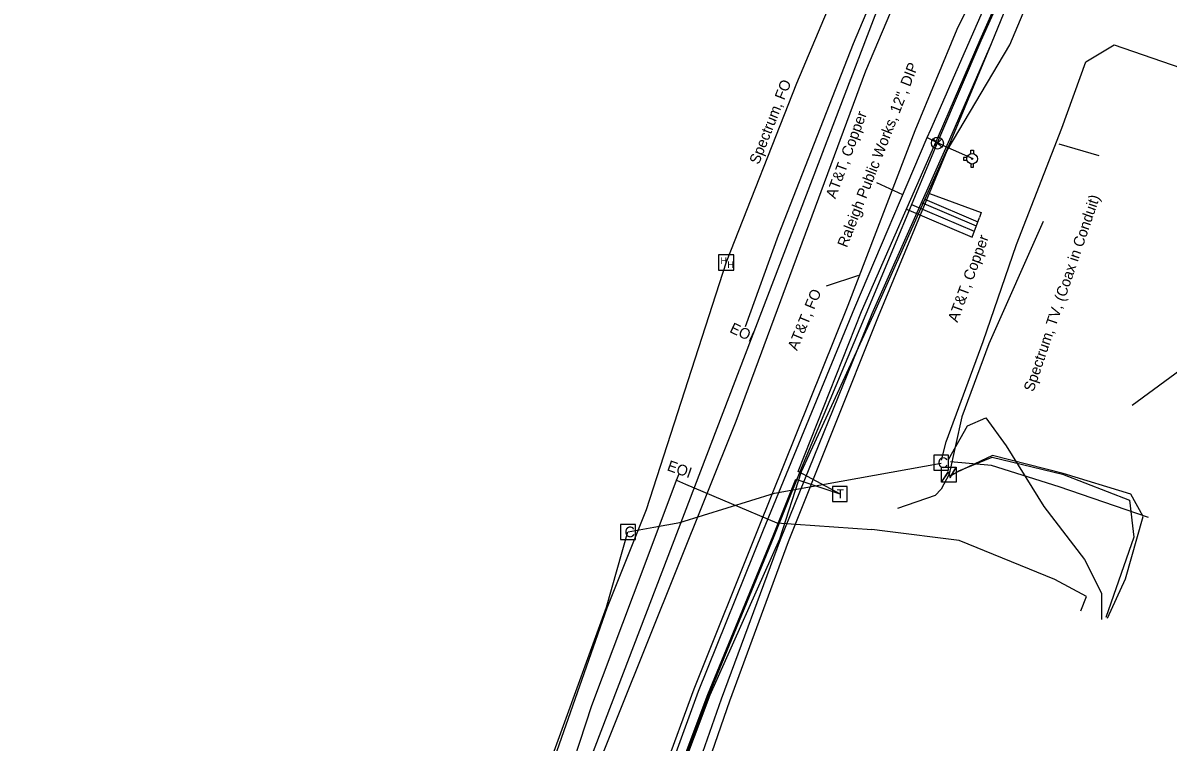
# Model space of a CAD drawing. Extents: x 2070721 to 2083039, y 729290 to 737883.
# Drawn here: x 2081151.9 to 2081580.5, y 733973 to 734242 of the extents above; entities that cross this region are included whole.
import ezdxf

# ---------------------------------------------------------------- set-up
doc = ezdxf.new("R2010")
doc.units = 0
for name, color, linetype in [('Cogo Default Point CELL', 7, 'Continuous'), ('COGO Default Point Elevation', 7, 'Continuous'), ('COGO Default Point Number', 7, 'Continuous'), ('Exist Utilities Gas UG Line SUE Cogo Point CELL', 7, 'Continuous'), ('Exist Utilities Gas UG Line SUE LOS B Cogo Comment', 7, 'Continuous'), ('Exist Utilities Gas UG Line SUE LOS B Cogo Point CELL', 7, 'Continuous'), ('Exist Utilities Gas Valve Cogo Elevation', 7, 'Continuous'), ('Exist Utilities Other Unknown UG SUE Cogo Point CELL', 7, 'Continuous'), ('Exist Utilities Power UG Cable SUE LOS B Cogo Elevation', 7, 'Continuous'), ('Exist Utilities Power UG Cable SUE LOS B Cogo Point CELL', 7, 'Continuous'), ('Exist Utilities Telephone UG Cable Cogo Point CELL', 7, 'Continuous'), ('Exist Utilities Telephone UG Cable SUE LOS C Cogo Comment', 7, 'Continuous'), ('Exist Utilities Telephone UG Cable SUE LOS C Cogo Number', 7, 'Continuous'), ('Exist Utilities Telephone UG FO SUE LOS B Cogo Comment', 7, 'Continuous'), ('Exist Utilities TV Hand Hole CELL', 7, 'Continuous'), ('Exist Utilities TV Pedestal CELL', 7, 'Continuous'), ('Exist Utilities TV Pedestal Cogo Elevation', 7, 'Continuous'), ('Exist Utilities TV Pedestal Cogo Number', 7, 'Continuous'), ('Exist Utilities TV UG Cable Cogo Point CELL', 7, 'Continuous'), ('Exist Utilities TV UG Cable SUE LOS C Cogo Comment', 7, 'Continuous'), ('Exist Utilities TV UG Cable SUE LOS C Cogo Elevation', 7, 'Continuous'), ('Exist Utilities TV UG Cable SUE LOS C Cogo Number', 7, 'Continuous'), ('Exist Utilities TV UG Cable SUE LOS C Cogo Point CELL', 7, 'Continuous'), ('Exist Utilities Water Manhole Cogo Elevation', 7, 'Continuous'), ('Exist Utilities Water Manhole Cogo Number', 7, 'Continuous'), ('Exist Utilities Water Meter Cogo Number', 7, 'Continuous')]:
    doc.layers.add(name, color=color, linetype=linetype)

msp = doc.modelspace()

# ---------------------------------------------------------------- linework, layer by layer
at = {"layer": 'Cogo Default Point CELL'}
for p, q in [((2081495.55, 734077.52), (2081495.55, 734077.52)), ((2081378.38, 734051.63), (2081378.38, 734051.63))]:
    msp.add_line(p, q, dxfattribs=at)
for points in [[(2081492.78, 734074.75), (2081498.33, 734074.75), (2081498.33, 734080.3), (2081492.78, 734080.3), (2081492.78, 734074.75)], [(2081375.61, 734048.85), (2081381.16, 734048.85), (2081381.16, 734054.4), (2081375.61, 734054.4), (2081375.61, 734048.85)]]:
    msp.add_lwpolyline(points, dxfattribs=at)
at = {"layer": 'COGO Default Point Elevation'}
msp.add_lwpolyline([(2081495.74, 734198.64), (2081492.59, 734195.49), (2081494.16, 734197.07), (2081495.74, 734195.49), (2081492.59, 734198.64)], dxfattribs=at)
msp.add_circle((2081494.16, 734197.07), 2.23, dxfattribs=at)
at = {"layer": 'COGO Default Point Number'}
msp.add_line((2081507.14, 734191.19), (2081507.14, 734191.19), dxfattribs=at)
for points in [[(2081505.23, 734191.7), (2081503.94, 734191.7), (2081503.94, 734190.67), (2081505.23, 734190.67)], [(2081506.62, 734193.1), (2081506.62, 734194.39), (2081507.65, 734194.39), (2081507.65, 734193.07)], [(2081506.62, 734189.27), (2081506.62, 734187.99), (2081507.65, 734187.99), (2081507.65, 734189.3)]]:
    msp.add_lwpolyline(points, dxfattribs=at)
for radius in [1.98, 0.243]:
    msp.add_circle((2081507.14, 734191.19), radius, dxfattribs=at)
at = {"layer": 'Exist Utilities Gas Valve Cogo Elevation'}
for p, q in [((2081488.23, 734174.81), (2081508.68, 734166.13)), ((2081489.45, 734176.03), (2081509.23, 734167.66)), ((2081484.48, 734174.03), (2081507.94, 734164.17))]:
    msp.add_line(p, q, dxfattribs=at)
for points in [[(2081491.14, 734178.26), (2081510.46, 734171.14), (2081509.82, 734169.24)], [(2081482.62, 734172.39), (2081507.12, 734161.92), (2081509.82, 734169.24)]]:
    msp.add_lwpolyline(points, dxfattribs=at)
at = {"layer": 'Exist Utilities Other Unknown UG SUE Cogo Point CELL'}
msp.add_line((2081539.58, 734196.78), (2081554.51, 734192.46), dxfattribs=at)
at = {"layer": 'Exist Utilities Telephone UG Cable Cogo Point CELL'}
msp.add_line((2081415.06, 734152.42), (2081415.06, 734152.42), dxfattribs=at)
msp.add_lwpolyline([(2081412.19, 734149.55), (2081417.94, 734149.55), (2081417.94, 734155.3), (2081412.19, 734155.3), (2081412.19, 734149.55)], dxfattribs=at)
at = {"layer": 'Exist Utilities Telephone UG Cable SUE LOS C Cogo Comment'}
for points in [[(2081306.2, 733834.68), (2081331.52, 733896.97), (2081357.74, 733949.48), (2081551.49, 734455.55)], [(2081422.3, 734128.51), (2081434.71, 734162.6), (2081462.76, 734234.36), (2081499.05, 734320.38), (2081503.56, 734331.04)]]:
    msp.add_lwpolyline(points, dxfattribs=at)
at = {"layer": 'Exist Utilities Telephone UG Cable SUE LOS C Cogo Number'}
msp.add_line((2081498.49, 734073.2), (2081498.49, 734073.2), dxfattribs=at)
msp.add_lwpolyline([(2081495.64, 734075.81), (2081501.2, 734075.81), (2081501.2, 734070.26), (2081495.64, 734070.26)], close=True, dxfattribs=at)
for points in [[(2081495.64, 734070.26), (2081498.29, 734074.2), (2081498.92, 734071.99), (2081501.2, 734075.81)], [(2081495.71, 734070.26), (2081498.29, 734073.99), (2081498.87, 734071.81), (2081501.2, 734075.66)]]:
    msp.add_lwpolyline(points, dxfattribs=at)
at = {"layer": 'Exist Utilities Telephone UG FO SUE LOS B Cogo Comment'}
msp.add_line((2081457.55, 734065.88), (2081457.55, 734065.88), dxfattribs=at)
msp.add_lwpolyline([(2081454.82, 734063.06), (2081460.42, 734063.06), (2081460.42, 734068.65), (2081454.82, 734068.65), (2081454.82, 734063.06)], dxfattribs=at)
at = {"layer": 'Exist Utilities TV Hand Hole CELL'}
msp.add_line((2081481.14, 734177.71), (2081471.52, 734182.16), dxfattribs=at)
at = {"layer": 'Exist Utilities TV Pedestal CELL'}
msp.add_lwpolyline([(2081305.07, 733834.62), (2081318.51, 733883.96), (2081344.94, 733950.24), (2081370.6, 734023.22), (2081385.26, 734060), (2081415.18, 734152.65), (2081441.55, 734219.41), (2081473.57, 734295.5), (2081490.54, 734320.82), (2081495.24, 734327.83)], dxfattribs=at)
at = {"layer": 'Exist Utilities TV Pedestal Cogo Elevation'}
for points in [[(2081490.29, 734199.14), (2081491.68, 734202.17), (2081522.1, 734271.61), (2081541.68, 734313.21), (2081545.19, 734320.14)], [(2081335.25, 733795.02), (2081336.53, 733799.05), (2081370.86, 733898.95), (2081404.78, 733992.12), (2081429.05, 734052.38), (2081463.19, 734135.61), (2081490.29, 734199.14)], [(2081490.29, 734199.14), (2081496.9, 734195.96), (2081507.42, 734191.29)]]:
    msp.add_lwpolyline(points, dxfattribs=at)
at = {"layer": 'Exist Utilities TV Pedestal Cogo Number'}
for points in [[(2081338.03, 733905.19), (2081338.21, 733905.54), (2081364.78, 733986.66), (2081384.36, 734038.69), (2081396.54, 734070.93), (2081397.51, 734073.37)], [(2081396.54, 734070.93), (2081399.83, 734069.53), (2081434.09, 734054.98), (2081469.65, 734052.56)], [(2081547.78, 734022.11), (2081549.89, 734027.5), (2081538.01, 734033.8), (2081502.22, 734048.37), (2081474.49, 734051.91), (2081469.65, 734052.56)]]:
    msp.add_lwpolyline(points, dxfattribs=at)
at = {"layer": 'Exist Utilities TV UG Cable Cogo Point CELL'}
for points in [[(2080953.21, 732796.69), (2081054.09, 733077.62), (2081111.09, 733245.57), (2081176.08, 733423.78), (2081231.97, 733580.28), (2081320.16, 733847.08), (2081418.84, 734093.09), (2081467.34, 734224.03), (2081494.06, 734287.2), (2081526.74, 734352.01), (2081556, 734404.62), (2081808.13, 734757.73), (2081845.73, 734804.26), (2081874.67, 734821.58), (2081898.66, 734810.94), (2081917.15, 734795.51)], [(2081296.4, 733658.15), (2081287.8, 733664.8), (2081303.6, 733706.37), (2081324.3, 733763.14), (2081337.34, 733798.98), (2081373.91, 733899.45), (2081408.19, 733990.78), (2081432.67, 734050.1), (2081441.11, 734071.31), (2081457.65, 734065.9), (2081441.97, 734074.17), (2081465.76, 734134.1), (2081494.56, 734199.64), (2081510.1, 734235.63), (2081525.23, 734269.67), (2081532.48, 734287.03), (2081544.5, 734311.63), (2081547.42, 734317.11)], [(2081296.31, 733658.4), (2081289.16, 733664.06), (2081304.03, 733706.05), (2081324.8, 733762.93), (2081337.87, 733799.07), (2081374.5, 733899.39), (2081408.89, 733991.2), (2081433.1, 734049.99), (2081442.72, 734074.23), (2081467.51, 734133.17), (2081494.99, 734199.31), (2081510.48, 734235.4), (2081525.69, 734269.34), (2081544.76, 734311.53), (2081547.99, 734317.07)], [(2081296.39, 733658.2), (2081307.45, 733685.25), (2081318.77, 733704.29), (2081345.73, 733792.08), (2081384.21, 733895.19), (2081416.52, 733988.47), (2081438.43, 734048.05), (2081472.15, 734132.3), (2081497.77, 734194.3), (2081521.27, 734233.79), (2081552.24, 734307.58), (2081554.35, 734311.73)], [(2081296.32, 733658.45), (2081292.23, 733667.87), (2081304.13, 733678.02), (2081310.51, 733703.91), (2081344.1, 733799.36), (2081380.98, 733896.99), (2081413.3, 733989.25), (2081435.43, 734048.8), (2081469.68, 734133.31), (2081498.8, 734198.46), (2081514.35, 734234.28), (2081535.34, 734285.71)], [(2081296.61, 733659.46), (2081294.36, 733663.37), (2081305.04, 733689.21), (2081304.27, 733706.32), (2081325.1, 733762.82), (2081338.41, 733798.86), (2081374.68, 733899.14), (2081409.12, 733990.75), (2081435.11, 734049.06), (2081443.22, 734074.28), (2081470.18, 734132.86), (2081499.3, 734198.06), (2081514.4, 734234.31)]]:
    msp.add_lwpolyline(points, dxfattribs=at)
at = {"layer": 'Exist Utilities TV UG Cable SUE LOS C Cogo Comment'}
for points in [[(2081566.99, 734098.99), (2081593.32, 734118.39), (2081609.81, 734133.03), (2081619.44, 734166.59), (2081611.13, 734190.33), (2081606.68, 734198.77)], [(2081533.76, 734167.78), (2081513.41, 734122.01), (2081503.32, 734094.68), (2081498.5, 734073.2)], [(2081557.74, 734019.38), (2081564.5, 734034.09), (2081571.11, 734057.42), (2081566.57, 734065.71), (2081541.21, 734073.53), (2081514.71, 734080.22), (2081499.18, 734072.89)], [(2081499.39, 734072.79), (2081502.13, 734074.42), (2081514.62, 734079.56), (2081541, 734073.24), (2081566.01, 734063.53), (2081567.68, 734049.7), (2081557.19, 734019.59)], [(2081498.49, 734073.2), (2081495.51, 734067.56), (2081493.34, 734065.2), (2081479.14, 734060.39)]]:
    msp.add_lwpolyline(points, dxfattribs=at)
at = {"layer": 'Exist Utilities TV UG Cable SUE LOS C Cogo Elevation'}
msp.add_lwpolyline([(2081311.88, 733857.73), (2081318.02, 733883.97), (2081343.7, 733950.47), (2081370.25, 734023.44), (2081378.31, 734051.68)], dxfattribs=at)
at = {"layer": 'Exist Utilities TV UG Cable SUE LOS C Cogo Number'}
for points in [[(2081495.68, 734078.41), (2081497.44, 734085.32), (2081511.29, 734122.81), (2081523.68, 734159.18), (2081540.68, 734202.67), (2081549.71, 734227.45), (2081560.24, 734233.78), (2081599.68, 734220.27), (2081626.49, 734212.19), (2081636.02, 734210.48)], [(2081498.25, 734078.67), (2081505.35, 734091.29), (2081512.22, 734094.34), (2081519.8, 734083.82), (2081533.95, 734061.11), (2081549.19, 734041.27), (2081555.57, 734028.72), (2081555.57, 734018.83)], [(2081378.38, 734051.63), (2081388.01, 734053.44), (2081397.72, 734055.21), (2081433.17, 734066.11), (2081495.5, 734077.4)], [(2081573.07, 734056.98), (2081539.64, 734068.54), (2081514.32, 734076.46), (2081498.99, 734077.79)]]:
    msp.add_lwpolyline(points, dxfattribs=at)
at = {"layer": 'Exist Utilities TV UG Cable SUE LOS C Cogo Point CELL'}
msp.add_lwpolyline([(2081248.81, 733567.64), (2081281.2, 733657.22), (2081333.49, 733797.21), (2081369.06, 733900.16), (2081403.11, 733993), (2081427.18, 734053.08), (2081460.75, 734136.42), (2081485.85, 734201.8), (2081501.51, 734239.63), (2081538.45, 734313.8), (2081542.88, 734322.62)], dxfattribs=at)
at = {"layer": 'Exist Utilities Water Manhole Cogo Elevation'}
msp.add_line((2081464.59, 734147.47), (2081452.54, 734143.52), dxfattribs=at)

# ---------------------------------------------------------------- texts
at = {"layer": 'Cogo Default Point CELL'}
for p in [(2081494.24, 734075.52), (2081377.08, 734049.63)]:
    msp.add_text('C', height=4, dxfattribs=at).set_placement(p)
at = {"layer": 'Exist Utilities Gas UG Line SUE Cogo Point CELL'}
msp.add_text('Raleigh Public Works, 12", DIP ', height=4, rotation=68.5923, dxfattribs=at).set_placement((2081460.26, 734157.73))
at = {"layer": 'Exist Utilities Gas UG Line SUE LOS B Cogo Comment'}
msp.add_text('AT&T, FO', height=4, rotation=67.5105, dxfattribs=at).set_placement((2081441.61, 734119.19))
at = {"layer": 'Exist Utilities Gas UG Line SUE LOS B Cogo Point CELL'}
msp.add_text('Spectrum, FO ', height=4, rotation=68.4413, dxfattribs=at).set_placement((2081427.32, 734188.83))
at = {"layer": 'Exist Utilities Power UG Cable SUE LOS B Cogo Elevation'}
msp.add_text('EOI', height=4, rotation=340.6445, dxfattribs=at).set_placement((2081392.69, 734074.74))
at = {"layer": 'Exist Utilities Power UG Cable SUE LOS B Cogo Point CELL'}
msp.add_text('EOI', height=4, rotation=335.0433, dxfattribs=at).set_placement((2081416.08, 734126.45))
at = {"layer": 'Exist Utilities Telephone UG Cable Cogo Point CELL'}
for p in [(2081412.98, 734151.77), (2081415.55, 734150.31)]:
    msp.add_text('H', height=2.5, dxfattribs=at).set_placement(p)
at = {"layer": 'Exist Utilities Telephone UG FO SUE LOS B Cogo Comment'}
msp.add_text('T', height=3.42, dxfattribs=at).set_placement((2081456.42, 734064.17))
at = {"layer": 'Exist Utilities Water Manhole Cogo Number'}
msp.add_text('Spectrum, TV, (Coax in Conduit)', height=4, rotation=71.1906, dxfattribs=at).set_placement((2081530.06, 734103.77))
at = {"layer": 'Exist Utilities Water Meter Cogo Number'}
for rotation, p in [(69.6741, (2081455.95, 734176)), (69.8365, (2081501.65, 734129.74))]:
    msp.add_text('AT&T, Copper', height=4, rotation=rotation, dxfattribs=at).set_placement(p)

doc.saveas('drawing.dxf')
